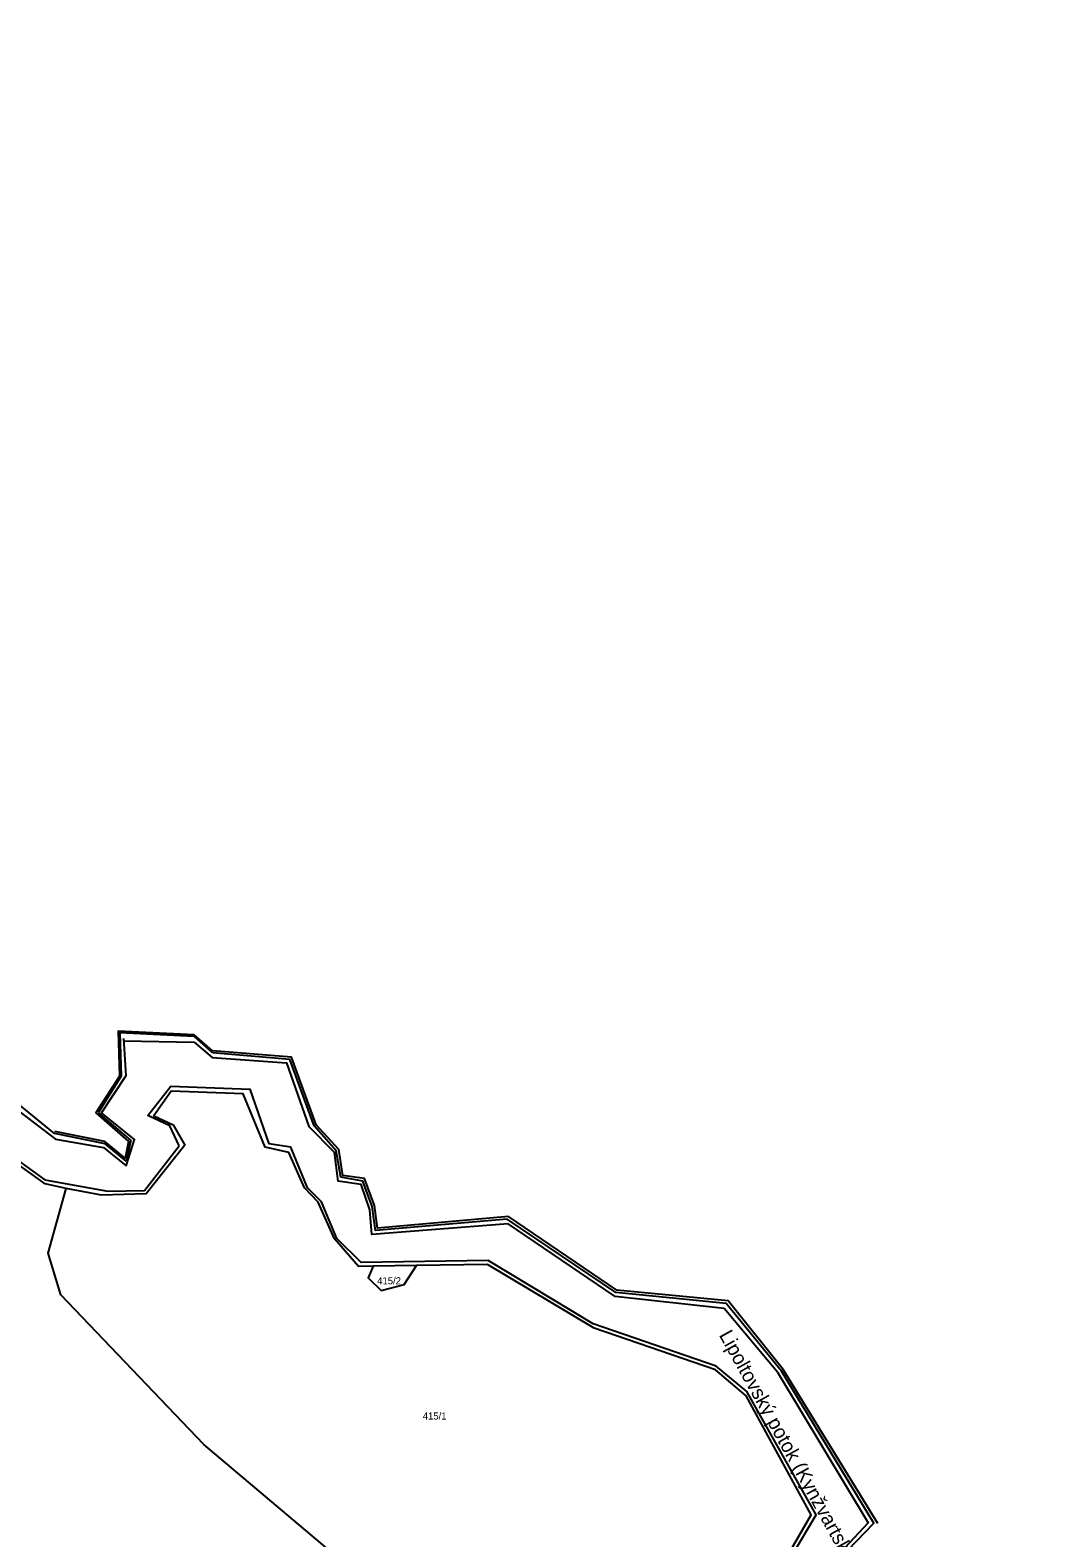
# Model space of a CAD drawing. Extents: x -880531 to -877616, y -1023932 to -1021350.
# Drawn here: x -880093.6 to -879852.6, y -1022219 to -1021858.6 of the extents above; entities that cross this region are included whole.
import ezdxf

# ---------------------------------------------------------------- set-up
doc = ezdxf.new("R2010")
doc.units = 0
for name, color, linetype in [('Hranice parcel', 7, 'Continuous'), ('Parcelní čísla', 7, 'Continuous'), ('Pop  PČ popisy', 7, 'Continuous'), ('Vnitřní kresba', 7, 'Continuous')]:
    doc.layers.add(name, color=color, linetype=linetype)

msp = doc.modelspace()

# ---------------------------------------------------------------- linework, layer by layer
at = {"layer": 'Hranice parcel'}
for p, q in [((-880050, -1022103.05), (-880054.37, -1022099.2)), ((-880071.85, -1022108.67), (-880077.33, -1022117.44)), ((-880077.33, -1022117.44), (-880069.55, -1022124)), ((-880069.55, -1022124), (-880070.63, -1022128.95)), ((-880001.2, -1022153.91), (-880011.61, -1022154.07))]:
    msp.add_line(p, q, dxfattribs=at)
for points in [[(-880085.05, -1022135.52), (-880090.05, -1022134.35), (-880114.59, -1022116.83), (-880124.2, -1022095.94), (-880123.09, -1022074.55), (-880119.83, -1022067.14), (-880113.21, -1022063.51), (-880135.34, -1022057.68), (-880144.49, -1022042.42), (-880173.19, -1022034.51), (-880188.01, -1022013.6), (-880190.67, -1022011.77), (-880204.69, -1021997.63), (-880203.31, -1021985.41), (-880206.9, -1021974.86), (-880225.75, -1021962.09), (-880261.05, -1021917.27), (-880260.44, -1021898.17), (-880256.82, -1021879.89), (-880255.85, -1021863.35), (-880256.94, -1021858.64)], [(-880070.63, -1022128.95), (-880075.72, -1022124.82), (-880087.84, -1022122.31), (-880105.7, -1022107.84), (-880111.94, -1022094.26), (-880114.03, -1022080.48)], [(-880054.37, -1022099.2), (-880072.18, -1022098.28), (-880071.85, -1022108.67)], [(-880019.31, -1022132.76), (-880020.4, -1022126.51), (-880025.67, -1022120.5), (-880031.56, -1022104.67), (-880050, -1022103.05)], [(-880011.61, -1022154.07), (-880015.12, -1022154.13), (-880020.8, -1022147.54), (-880024.73, -1022138.79), (-880028.02, -1022135.34), (-880031.74, -1022126.89), (-880037.4, -1022125.64), (-880042.66, -1022112.89), (-880059.92, -1022112.26), (-880064.07, -1022118.09), (-880059.39, -1022120.28), (-880056.66, -1022125.17), (-880065.89, -1022136.76), (-880076.54, -1022137.08), (-880085.05, -1022135.52)], [(-880011.84, -1022139.78), (-880014.09, -1022133.76), (-880019.31, -1022132.76)], [(-879998.66, -1022241.71), (-880052.08, -1022196.68), (-880086.25, -1022160.89), (-880089.28, -1022150.93), (-880085.05, -1022135.52)], [(-879852.62, -1022356.1), (-879876.34, -1022331.08), (-879900.8, -1022319.74), (-879917.41, -1022273.06), (-879904.07, -1022228.12), (-879891.86, -1022215.5), (-879913.95, -1022179.12), (-879927.16, -1022162.97), (-879953.53, -1022160.38), (-879979.51, -1022142.78), (-880011, -1022145.56), (-880011.84, -1022139.78)], [(-880011.61, -1022154.07), (-880012.81, -1022156.88), (-880009.68, -1022159.88), (-880004.2, -1022158.45), (-880001.2, -1022153.91)], [(-879914.25, -1022226.31), (-879906.81, -1022213.47), (-879922.39, -1022185.03), (-879929.69, -1022178.8), (-879958.73, -1022168.9), (-879984.23, -1022153.64), (-880001.2, -1022153.91)]]:
    msp.add_lwpolyline(points, dxfattribs=at)
at = {"layer": 'Vnitřní kresba'}
for p, q in [((-880071.2, -1022100.2), (-880054.44, -1022100.49)), ((-880054.44, -1022100.49), (-880050.09, -1022104.18)), ((-880106.32, -1022109.44), (-880087.55, -1022123.67)), ((-880087.55, -1022123.67), (-880076.07, -1022125.72)), ((-880076.07, -1022125.72), (-880070.66, -1022130.06))]:
    msp.add_line(p, q, dxfattribs=at)
for points in [[(-879890.92, -1022215.58), (-879913.54, -1022178.76), (-879926.65, -1022162.35), (-879953.28, -1022159.78), (-879979.23, -1022142.16), (-880010.58, -1022145), (-880011.27, -1022139.53), (-880013.7, -1022133.1), (-880018.82, -1022132.41), (-880019.77, -1022126.16), (-880025.24, -1022120.26), (-880031.14, -1022104.11), (-880050.02, -1022102.59), (-880054.38, -1022098.78), (-880072.59, -1022097.91), (-880072.27, -1022108.61), (-880077.92, -1022117.39), (-880070.07, -1022124.28), (-880070.94, -1022128.27), (-880075.76, -1022124.28), (-880087.7, -1022121.89)], [(-880070.66, -1022130.06), (-880068.7, -1022123.78), (-880076.57, -1022117.38), (-880070.67, -1022108.45), (-880071.24, -1022099.67)], [(-880050.09, -1022104.18), (-880032.31, -1022105.49), (-880027, -1022120.71)], [(-880057.96, -1022125.31), (-880060.26, -1022120.5), (-880065.5, -1022118.04), (-880060.01, -1022111.07), (-880041.08, -1022111.72), (-880036.54, -1022124.85)], [(-880113.7, -1022116.41), (-880090.09, -1022133.42), (-880075.01, -1022136.13), (-880066.24, -1022135.97), (-880057.96, -1022125.31)], [(-879914.9, -1022179.41), (-879927.62, -1022164.14), (-879953.7, -1022161.28), (-879979.3, -1022143.94), (-880011.89, -1022146.48), (-880012.37, -1022140.6), (-880014.44, -1022134.55), (-880020, -1022133.76), (-880020.8, -1022126.92), (-880027, -1022120.71)], [(-879913.63, -1022226.83), (-879905.68, -1022213.45), (-879922.21, -1022184.03), (-879929.53, -1022177.98), (-879958.94, -1022167.8), (-879984.07, -1022152.69), (-880014.44, -1022153.17), (-880020.32, -1022147.44), (-880023.98, -1022138.69), (-880027.31, -1022135.35), (-880031.29, -1022125.65), (-880036.54, -1022124.85)], [(-879914.9, -1022179.41), (-879893.18, -1022215.36), (-879905.4, -1022228.48)]]:
    msp.add_lwpolyline(points, dxfattribs=at)

# ---------------------------------------------------------------- texts
at = {"layer": 'Parcelní čísla'}
for s, p in [('415/2', (-880010.63, -1022158.39)), ('415/1', (-879999.73, -1022190.71))]:
    msp.add_text(s, height=1.7, dxfattribs=at).set_placement(p)
at = {"layer": 'Pop  PČ popisy'}
msp.add_text('Lipoltovský potok (Kynžvartský potok)', height=3.4, rotation=299, dxfattribs=at).set_placement((-879928.959, -1022170.509))

doc.saveas('drawing.dxf')
